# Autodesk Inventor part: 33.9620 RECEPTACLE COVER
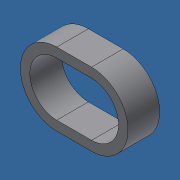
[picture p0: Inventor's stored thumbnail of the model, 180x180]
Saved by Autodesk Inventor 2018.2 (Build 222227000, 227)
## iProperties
Created: 2018-05
Part Number: 33.9620 RECEPTACLE COVER
Material: Generic
Document SubType Name: Modeling
Designer: amoles
Density: 1 g/cm^3
Appearance: White
Author: amoles
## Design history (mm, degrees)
sketch "Sketch1"
  geometry: L1 (-2.2, 4.6)-(2.2, 4.6); L2 (2.2, -4.6)-(-2.2, -4.6); L3 (-2.2, -3.4)-(2.2, -3.4); L4 (2.2, 3.4)-(-2.2, 3.4); A1 r 4.6 centre (2.2, 0) between (2.2, -4.6) and (2.2, 4.6); A2 r 4.6 centre (2.2, 0) between (2.2, -4.6) and (2.2, 4.6); A3 r 4.6 centre (-2.2, 0) between (-2.2, 4.6) and (-2.2, -4.6); A4 r 3.4 centre (2.2, 0) between (2.2, -3.4) and (2.2, 3.4); A5 r 3.4 centre (-2.2, 0) between (-2.2, 3.4) and (-2.2, -3.4); 1 further point
  constraints: 10 point on circle, 8 end point, 8 tangent, 5 centre point, 3 horizontal alignment, 2 concentric, 2 equal radius
  dimensions: "d2" = 4.4 distance of A1.centre A3.centre; "d3" = 4.6 radius of A1; "d4" = 3.4 radius of A4; "d5" = 2.2 distance of point (0, 0) A3.centre (= 0.5 x d2)
extrude "Extrusion1" new body sketch "Sketch1" distance "d0" = 4; taper "d1" = 0 deg
sketch "Sketch2"
  geometry: L1 (-8, 6.5)-(8, 6.5); L2 (8, 6.5)-(8, -6.5); L3 (8, -6.5)-(-8, -6.5); L4 (-8, -6.5)-(-8, 6.5); A1 r 3.4 centre (-2.2, 0) between (-2.2, 3.4) and (-2.2, -3.4) reference; 3 further points
  constraints: 8 end point, 2 midpoint, 2 parallel, 1 horizontal, 1 horizontal alignment, 1 perpendicular, 1 vertical alignment
  dimensions: "d6" = 16 distance of L1.start L1.end; "d7" = 13 distance of L1.end L2.end
extrude "Extrusion2" join sketch "Sketch2" distance "d8" = 2; taper "d9" = 0 deg
fillet "Fillet1" dims "d10" = 2
body "Solid1"
